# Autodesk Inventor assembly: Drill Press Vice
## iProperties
Shininess: 64.0
Length Units: 11269
Angle Units: 11279
Time Units: 11290
Mass Units: 11283
Length Display Precision: 3
Angle Display Precision: 2
Created: 2002-02
Part Number: Drill Press Vice
Document SubType Name: Assembly
Designer: ***
Density: 0.0
Volumn: 0.0
Area: 0.0
PropertySet Name: Model Information
Control State: 0
Master: False
Checked Out: False
Author: ***
